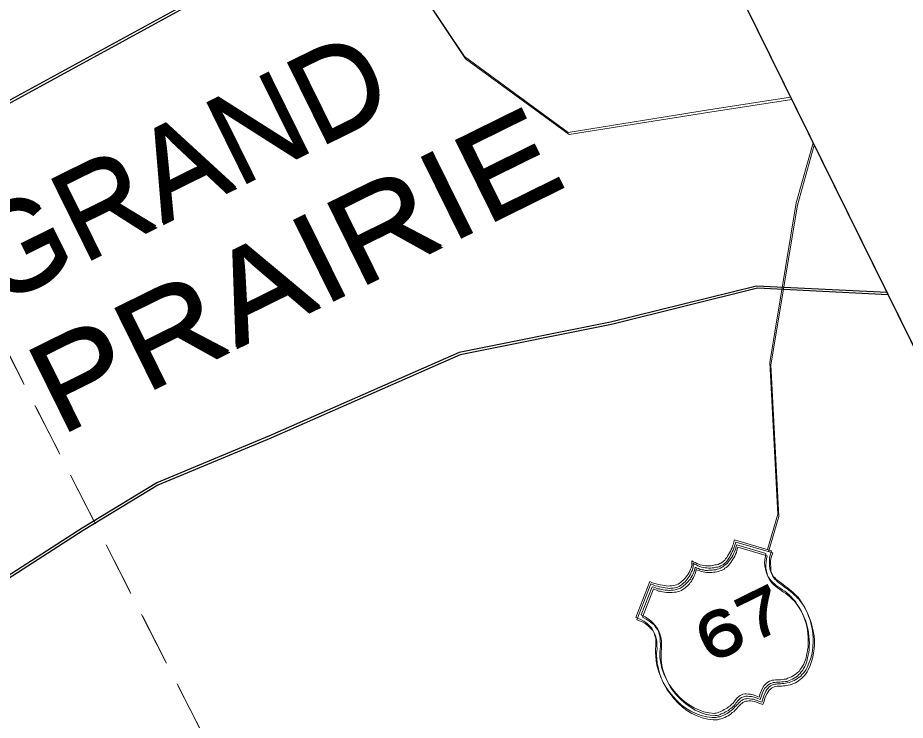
# Model space of a CAD drawing. Extents: x 2356606 to 2371222, y 6973096 to 6982644.
# Drawn here: x 2357437.7 to 2357539.9, y 6973680.4 to 6973761.2 of the extents above; entities that cross this region are included whole.
import ezdxf

# ---------------------------------------------------------------- set-up
doc = ezdxf.new("R2010")
doc.units = 0
doc.header["$LTSCALE"] = 2
doc.linetypes.add('MEDIUM_DASHED', pattern=[4.5, 3, -1.5])
doc.layers.add('62', color=7, linetype='Continuous', lineweight=13)
doc.layers.add('63', color=7, linetype='Continuous', lineweight=13)

msp = doc.modelspace()

# ---------------------------------------------------------------- linework, layer by layer
at = {"layer": '62', "linetype": 'MEDIUM_DASHED'}
msp.add_line((2357358.049, 6973876.711), (2357485.75, 6973626.399), dxfattribs=at)
at = {"layer": '62'}
msp.add_line((2357525.309, 6973703.86), (2357524.132, 6973699.792), dxfattribs=at)
at = {"layer": '62', "lineweight": 25}
for points in [[(2356999.05, 6973805.301), (2357204.965, 6973388.075), (2357608.13, 6973587.05), (2357402.214, 6974004.278)], [(2357505.855, 6973794.281), (2357494.638, 6973787.314), (2357477.945, 6973775.941), (2357457.618, 6973762.773), (2357434.819, 6973750.341), (2357408.769, 6973737.485), (2357380.527, 6973722.566), (2357364.72, 6973713.512)], [(2357537.893, 6973729.369), (2357522.87, 6973730.109), (2357506.064, 6973725.93), (2357488.655, 6973722.457), (2357466.842, 6973712.87), (2357453.859, 6973707.442), (2357445.268, 6973702.223), (2357430.768, 6973692.911), (2357420.094, 6973687.642), (2357412.343, 6973683.163)]]:
    msp.add_lwpolyline(points, dxfattribs=at)
at = {"layer": '62'}
for points in [[(2357526.798, 6973751.846), (2357517.36, 6973750.375), (2357501.195, 6973747.794), (2357489.256, 6973756.529), (2357484.812, 6973763.194), (2357480.012, 6973771.04), (2357477.267, 6973777.212), (2357474.788, 6973784.368), (2357471.174, 6973790.063), (2357467.234, 6973798.409)], [(2357529.386, 6973746.597), (2357527.44, 6973739.666), (2357524.387, 6973721.297), (2357525.309, 6973703.86)], [(2357508.987, 6973691.941), (2357510.58, 6973696.088), (2357510.83, 6973695.987), (2357511.082, 6973695.883), (2357511.332, 6973695.833), (2357511.572, 6973695.75), (2357511.797, 6973695.71), (2357512.035, 6973695.678), (2357512.237, 6973695.626), (2357512.478, 6973695.594), (2357512.689, 6973695.574), (2357512.882, 6973695.594), (2357513.103, 6973695.603), (2357513.284, 6973695.643), (2357513.495, 6973695.671), (2357513.657, 6973695.7), (2357513.84, 6973695.79), (2357514.008, 6973695.901), (2357514.12, 6973695.978), (2357514.232, 6973696.108), (2357514.382, 6973696.21), (2357514.524, 6973696.33), (2357514.648, 6973696.49), (2357514.758, 6973696.62), (2357514.88, 6973696.779), (2357515.001, 6973696.94), (2357515.103, 6973697.141), (2357515.195, 6973697.311), (2357515.266, 6973697.524), (2357515.366, 6973697.674), (2357515.408, 6973697.896), (2357515.439, 6973698.086), (2357515.44, 6973698.287), (2357515.441, 6973698.489), (2357515.621, 6973698.377), (2357515.825, 6973698.276), (2357516.003, 6973698.164), (2357516.214, 6973698.093), (2357516.404, 6973698.01), (2357516.616, 6973697.988), (2357516.818, 6973697.937), (2357517.028, 6973697.917), (2357517.23, 6973697.914), (2357517.441, 6973697.893), (2357517.652, 6973697.922), (2357517.844, 6973697.941), (2357518.065, 6973698.003), (2357518.238, 6973698.01), (2357518.458, 6973698.069), (2357518.639, 6973698.159), (2357518.781, 6973698.229), (2357518.942, 6973698.308), (2357519.053, 6973698.438), (2357519.216, 6973698.568), (2357519.318, 6973698.719), (2357519.448, 6973698.86), (2357519.541, 6973699.03), (2357519.663, 6973699.19), (2357519.745, 6973699.381), (2357519.866, 6973699.592), (2357519.946, 6973699.782), (2357520.05, 6973699.983), (2357520.11, 6973700.214), (2357520.221, 6973700.446), (2357520.265, 6973700.668), (2357520.345, 6973700.908), (2357524.605, 6973699.647), (2357524.471, 6973699.258), (2357524.359, 6973698.825), (2357524.345, 6973698.392), (2357524.375, 6973697.98), (2357524.405, 6973697.567), (2357524.521, 6973697.223), (2357524.632, 6973696.952), (2357524.74, 6973696.778), (2357524.842, 6973696.628), (2357525.001, 6973696.508), (2357525.131, 6973696.344), (2357525.321, 6973696.212), (2357525.52, 6973696.061), (2357525.725, 6973695.909), (2357525.933, 6973695.736), (2357526.174, 6973695.555), (2357526.405, 6973695.394), (2357526.635, 6973695.231), (2357526.864, 6973695.019), (2357527.075, 6973694.846), (2357527.295, 6973694.652), (2357527.466, 6973694.46), (2357527.657, 6973694.28), (2357527.796, 6973694.048), (2357528.126, 6973693.583), (2357528.417, 6973693.097), (2357528.644, 6973692.633), (2357528.841, 6973692.129), (2357529.028, 6973691.646), (2357529.159, 6973691.133), (2357529.276, 6973690.638), (2357529.356, 6973690.124), (2357529.403, 6973689.622), (2357529.402, 6973689.118)], [(2357528.7, 6973687.893), (2357528.749, 6973688.194), (2357528.802, 6973688.548), (2357528.805, 6973688.9), (2357528.819, 6973689.283), (2357528.797, 6973689.674), (2357528.772, 6973690.088), (2357528.732, 6973690.522), (2357528.655, 6973690.934), (2357528.537, 6973691.377), (2357528.397, 6973691.81), (2357528.24, 6973692.233), (2357528.03, 6973692.657), (2357527.791, 6973693.092), (2357527.56, 6973693.455), (2357527.34, 6973693.797), (2357527.102, 6973694.081), (2357526.85, 6973694.334), (2357526.611, 6973694.566), (2357526.351, 6973694.79), (2357526.111, 6973694.973), (2357525.849, 6973695.142), (2357525.589, 6973695.317), (2357525.378, 6973695.487), (2357525.148, 6973695.65), (2357524.938, 6973695.822), (2357524.728, 6973695.994), (2357524.557, 6973696.188), (2357524.396, 6973696.359), (2357524.236, 6973696.581), (2357524.096, 6973696.864), (2357523.977, 6973697.205), (2357523.89, 6973697.54), (2357523.82, 6973697.88), (2357523.793, 6973698.242), (2357523.834, 6973698.615), (2357523.887, 6973698.969), (2357523.957, 6973699.329), (2357520.604, 6973700.333), (2357520.531, 6973700.123), (2357520.48, 6973699.919), (2357520.42, 6973699.689), (2357520.339, 6973699.5), (2357520.236, 6973699.297), (2357520.134, 6973699.098), (2357520.025, 6973698.917), (2357519.911, 6973698.737), (2357519.769, 6973698.567), (2357519.658, 6973698.387), (2357519.514, 6973698.216), (2357519.395, 6973698.106), (2357519.233, 6973697.977), (2357519.102, 6973697.885), (2357519, 6973697.786), (2357518.859, 6973697.714), (2357518.717, 6973697.644), (2357518.525, 6973697.576), (2357518.356, 6973697.518), (2357518.182, 6973697.458), (2357517.97, 6973697.427), (2357517.8, 6973697.419), (2357517.589, 6973697.391), (2357517.388, 6973697.392), (2357517.216, 6973697.383), (2357516.965, 6973697.384), (2357516.794, 6973697.424), (2357516.604, 6973697.457), (2357516.384, 6973697.496), (2357516.212, 6973697.587), (2357516.011, 6973697.64), (2357515.801, 6973697.763), (2357515.759, 6973697.541), (2357515.729, 6973697.349), (2357515.647, 6973697.159), (2357515.574, 6973696.999), (2357515.503, 6973696.836), (2357515.423, 6973696.696), (2357515.312, 6973696.518), (2357515.262, 6973696.367), (2357515.117, 6973696.248), (2357515.018, 6973696.097), (2357514.895, 6973695.984), (2357514.784, 6973695.856), (2357514.653, 6973695.765), (2357514.521, 6973695.626), (2357514.391, 6973695.536), (2357514.259, 6973695.444), (2357514.106, 6973695.346), (2357513.905, 6973695.247), (2357513.726, 6973695.208), (2357513.501, 6973695.148), (2357513.291, 6973695.119), (2357513.048, 6973695.099), (2357512.809, 6973695.082), (2357512.616, 6973695.112), (2357512.366, 6973695.112), (2357512.135, 6973695.124), (2357511.914, 6973695.165), (2357511.702, 6973695.238), (2357511.461, 6973695.269), (2357511.239, 6973695.361)], [(2357510.87, 6973695.503), (2357509.612, 6973692.25), (2357510.043, 6973692.036), (2357510.384, 6973691.803), (2357510.695, 6973691.579), (2357510.956, 6973691.357), (2357511.166, 6973691.085), (2357511.356, 6973690.851), (2357511.516, 6973690.63), (2357511.607, 6973690.347), (2357511.674, 6973690.056), (2357511.754, 6973689.791), (2357511.802, 6973689.49), (2357511.799, 6973689.189), (2357511.81, 6973688.918), (2357511.808, 6973688.614), (2357511.775, 6973688.325), (2357511.755, 6973688.012), (2357511.76, 6973687.338), (2357511.858, 6973686.683), (2357511.985, 6973686.069), (2357512.213, 6973685.454), (2357512.493, 6973684.837), (2357512.81, 6973684.243), (2357513.2, 6973683.707), (2357513.621, 6973683.211), (2357514.091, 6973682.715), (2357514.601, 6973682.291), (2357515.124, 6973681.896), (2357515.685, 6973681.572), (2357516.228, 6973681.339), (2357516.82, 6973681.102), (2357517.402, 6973680.989), (2357517.986, 6973680.926), (2357518.097, 6973680.956), (2357518.229, 6973680.946), (2357518.389, 6973680.974), (2357518.552, 6973681.055), (2357518.672, 6973681.114), (2357518.846, 6973681.174), (2357519.005, 6973681.253), (2357519.157, 6973681.352), (2357519.338, 6973681.443), (2357519.499, 6973681.521), (2357519.631, 6973681.662), (2357519.782, 6973681.762), (2357519.933, 6973681.863), (2357520.045, 6973681.993), (2357520.167, 6973682.103), (2357520.267, 6973682.203), (2357520.37, 6973682.352), (2357520.46, 6973682.473), (2357520.551, 6973682.594), (2357520.652, 6973682.693), (2357520.784, 6973682.832), (2357520.876, 6973682.903), (2357521.005, 6973682.994), (2357521.147, 6973683.064), (2357521.301, 6973683.114), (2357521.52, 6973683.172), (2357521.692, 6973683.18), (2357521.914, 6973683.141), (2357522.165, 6973683.139), (2357522.467, 6973683.037), (2357522.807, 6973682.954), (2357523.159, 6973682.801), (2357523.302, 6973683.222), (2357523.445, 6973683.545), (2357523.559, 6973683.826), (2357523.709, 6973684.076), (2357523.872, 6973684.257), (2357524.002, 6973684.397), (2357524.163, 6973684.526), (2357524.346, 6973684.617), (2357524.517, 6973684.676), (2357524.669, 6973684.726), (2357524.859, 6973684.744), (2357525.051, 6973684.764), (2357525.241, 6973684.783), (2357525.423, 6973684.771), (2357525.633, 6973684.801), (2357525.856, 6973684.81), (2357526.057, 6973684.859), (2357526.278, 6973684.868), (2357526.481, 6973684.968), (2357526.672, 6973685.037), (2357526.884, 6973685.115), (2357527.076, 6973685.236), (2357527.247, 6973685.346), (2357527.44, 6973685.465), (2357527.588, 6973685.616), (2357527.773, 6973685.757), (2357527.895, 6973685.966), (2357528.056, 6973686.146), (2357528.16, 6973686.347), (2357528.301, 6973686.568), (2357528.402, 6973686.82), (2357528.503, 6973687.07), (2357528.564, 6973687.301), (2357528.618, 6973687.603), (2357528.7, 6973687.893)], [(2357511.239, 6973695.361), (2357511.048, 6973695.441), (2357510.87, 6973695.503)], [(2357509.91, 6973691.543), (2357509.499, 6973691.765), (2357508.987, 6973691.941)], [(2357529.402, 6973689.118), (2357529.366, 6973688.626), (2357529.304, 6973688.142), (2357529.223, 6973687.65), (2357529.069, 6973687.149), (2357528.894, 6973686.686), (2357528.701, 6973686.214), (2357528.568, 6973685.973), (2357528.427, 6973685.751), (2357528.274, 6973685.552), (2357528.102, 6973685.394), (2357527.961, 6973685.223), (2357527.779, 6973685.08), (2357527.577, 6973684.93), (2357527.407, 6973684.822), (2357527.215, 6973684.701), (2357527.001, 6973684.623), (2357526.822, 6973684.534), (2357526.62, 6973684.483), (2357526.388, 6973684.446), (2357526.215, 6973684.385), (2357526.026, 6973684.368), (2357525.833, 6973684.346), (2357525.642, 6973684.328), (2357525.47, 6973684.319), (2357525.289, 6973684.332), (2357525.127, 6973684.299), (2357524.967, 6973684.271), (2357524.786, 6973684.232), (2357524.635, 6973684.181), (2357524.473, 6973684.101), (2357524.332, 6973683.981), (2357524.2, 6973683.841), (2357524.069, 6973683.652), (2357523.957, 6973683.471), (2357523.815, 6973683.198), (2357523.692, 6973682.941), (2357523.61, 6973682.596), (2357523.478, 6973682.205), (2357523.136, 6973682.337), (2357522.815, 6973682.431), (2357522.534, 6973682.544), (2357522.292, 6973682.573), (2357522.071, 6973682.614), (2357521.859, 6973682.637), (2357521.698, 6973682.607), (2357521.528, 6973682.599), (2357521.395, 6973682.557), (2357521.254, 6973682.489), (2357521.162, 6973682.418), (2357521.042, 6973682.309), (2357520.932, 6973682.23), (2357520.83, 6973682.129), (2357520.72, 6973681.999), (2357520.598, 6973681.89), (2357520.528, 6973681.777), (2357520.386, 6973681.659), (2357520.255, 6973681.517), (2357520.123, 6973681.379), (2357519.951, 6973681.267), (2357519.811, 6973681.148), (2357519.627, 6973681.009), (2357519.476, 6973680.909), (2357519.273, 6973680.809), (2357519.112, 6973680.729), (2357518.912, 6973680.629), (2357518.679, 6973680.541), (2357518.468, 6973680.512), (2357518.245, 6973680.452), (2357518.005, 6973680.432), (2357517.751, 6973680.436), (2357517.14, 6973680.509), (2357516.504, 6973680.672), (2357515.892, 6973680.894), (2357515.301, 6973681.18), (2357514.728, 6973681.526), (2357514.218, 6973681.9), (2357513.737, 6973682.365), (2357513.266, 6973682.862), (2357512.866, 6973683.367), (2357512.474, 6973683.902), (2357512.138, 6973684.488), (2357511.849, 6973685.074), (2357511.611, 6973685.706), (2357511.443, 6973686.304), (2357511.326, 6973686.947), (2357511.268, 6973687.571), (2357511.248, 6973687.811), (2357511.25, 6973688.064), (2357511.262, 6973688.347), (2357511.294, 6973688.639), (2357511.276, 6973688.929), (2357511.277, 6973689.23), (2357511.271, 6973689.553), (2357511.179, 6973689.835), (2357511.1, 6973690.149), (2357510.951, 6973690.45), (2357510.811, 6973690.734), (2357510.551, 6973691.007), (2357510.29, 6973691.279), (2357509.91, 6973691.543)]]:
    msp.add_lwpolyline(points, dxfattribs=at)
at = {"layer": '63', "linetype": 'MEDIUM_DASHED'}
msp.add_line((2357357.919, 6973876.974), (2357485.62, 6973626.662), dxfattribs=at)
at = {"layer": '63'}
msp.add_line((2357525.179, 6973704.123), (2357524.002, 6973700.055), dxfattribs=at)
at = {"layer": '63', "lineweight": 25}
for points in [[(2356998.92, 6973805.564), (2357204.835, 6973388.338), (2357608, 6973587.313), (2357402.084, 6974004.541)], [(2357505.725, 6973794.544), (2357494.508, 6973787.577), (2357477.815, 6973776.204), (2357457.488, 6973763.036), (2357434.689, 6973750.604), (2357408.639, 6973737.748), (2357380.397, 6973722.829), (2357364.59, 6973713.775)], [(2357537.763, 6973729.632), (2357522.74, 6973730.372), (2357505.934, 6973726.193), (2357488.525, 6973722.72), (2357466.712, 6973713.133), (2357453.729, 6973707.705), (2357445.138, 6973702.486), (2357430.638, 6973693.174), (2357419.964, 6973687.905), (2357412.213, 6973683.426)]]:
    msp.add_lwpolyline(points, dxfattribs=at)
at = {"layer": '63'}
for points in [[(2357526.668, 6973752.109), (2357517.23, 6973750.638), (2357501.065, 6973748.057), (2357489.126, 6973756.792), (2357484.682, 6973763.457), (2357479.882, 6973771.303), (2357477.137, 6973777.475), (2357474.658, 6973784.631), (2357471.044, 6973790.326), (2357467.104, 6973798.672)], [(2357529.256, 6973746.86), (2357527.31, 6973739.929), (2357524.257, 6973721.56), (2357525.179, 6973704.123)], [(2357508.857, 6973692.204), (2357510.45, 6973696.351), (2357510.7, 6973696.25), (2357510.952, 6973696.146), (2357511.202, 6973696.096), (2357511.442, 6973696.013), (2357511.667, 6973695.973), (2357511.905, 6973695.941), (2357512.107, 6973695.889), (2357512.348, 6973695.857), (2357512.559, 6973695.837), (2357512.752, 6973695.857), (2357512.973, 6973695.866), (2357513.154, 6973695.906), (2357513.365, 6973695.934), (2357513.527, 6973695.963), (2357513.71, 6973696.053), (2357513.878, 6973696.164), (2357513.99, 6973696.241), (2357514.102, 6973696.371), (2357514.252, 6973696.473), (2357514.394, 6973696.593), (2357514.518, 6973696.753), (2357514.628, 6973696.883), (2357514.75, 6973697.042), (2357514.871, 6973697.203), (2357514.973, 6973697.404), (2357515.065, 6973697.574), (2357515.136, 6973697.787), (2357515.236, 6973697.937), (2357515.278, 6973698.159), (2357515.309, 6973698.349), (2357515.31, 6973698.55), (2357515.311, 6973698.752), (2357515.491, 6973698.64), (2357515.695, 6973698.539), (2357515.873, 6973698.427), (2357516.084, 6973698.356), (2357516.274, 6973698.273), (2357516.486, 6973698.251), (2357516.688, 6973698.2), (2357516.898, 6973698.18), (2357517.1, 6973698.177), (2357517.311, 6973698.156), (2357517.522, 6973698.185), (2357517.714, 6973698.204), (2357517.935, 6973698.266), (2357518.108, 6973698.273), (2357518.328, 6973698.332), (2357518.509, 6973698.422), (2357518.651, 6973698.492), (2357518.812, 6973698.571), (2357518.923, 6973698.701), (2357519.086, 6973698.831), (2357519.188, 6973698.982), (2357519.318, 6973699.123), (2357519.411, 6973699.293), (2357519.533, 6973699.453), (2357519.615, 6973699.644), (2357519.736, 6973699.855), (2357519.816, 6973700.045), (2357519.92, 6973700.246), (2357519.98, 6973700.477), (2357520.091, 6973700.709), (2357520.135, 6973700.931), (2357520.215, 6973701.171), (2357524.475, 6973699.91), (2357524.341, 6973699.521), (2357524.229, 6973699.088), (2357524.215, 6973698.655), (2357524.245, 6973698.243), (2357524.275, 6973697.83), (2357524.391, 6973697.486), (2357524.502, 6973697.215), (2357524.61, 6973697.041), (2357524.712, 6973696.891), (2357524.871, 6973696.771), (2357525.001, 6973696.607), (2357525.191, 6973696.475), (2357525.39, 6973696.324), (2357525.595, 6973696.172), (2357525.803, 6973695.999), (2357526.044, 6973695.818), (2357526.275, 6973695.657), (2357526.505, 6973695.494), (2357526.734, 6973695.282), (2357526.945, 6973695.109), (2357527.165, 6973694.915), (2357527.336, 6973694.723), (2357527.527, 6973694.543), (2357527.666, 6973694.311), (2357527.996, 6973693.846), (2357528.287, 6973693.36), (2357528.514, 6973692.896), (2357528.711, 6973692.392), (2357528.898, 6973691.909), (2357529.029, 6973691.396), (2357529.146, 6973690.901), (2357529.226, 6973690.387), (2357529.273, 6973689.885), (2357529.272, 6973689.381)], [(2357528.57, 6973688.156), (2357528.619, 6973688.457), (2357528.672, 6973688.811), (2357528.675, 6973689.163), (2357528.689, 6973689.546), (2357528.667, 6973689.937), (2357528.642, 6973690.351), (2357528.602, 6973690.785), (2357528.525, 6973691.197), (2357528.407, 6973691.64), (2357528.267, 6973692.073), (2357528.11, 6973692.496), (2357527.9, 6973692.92), (2357527.661, 6973693.355), (2357527.43, 6973693.718), (2357527.21, 6973694.06), (2357526.972, 6973694.344), (2357526.72, 6973694.597), (2357526.481, 6973694.829), (2357526.221, 6973695.053), (2357525.981, 6973695.236), (2357525.719, 6973695.405), (2357525.459, 6973695.58), (2357525.248, 6973695.75), (2357525.018, 6973695.913), (2357524.808, 6973696.085), (2357524.598, 6973696.257), (2357524.427, 6973696.451), (2357524.266, 6973696.622), (2357524.106, 6973696.844), (2357523.966, 6973697.127), (2357523.847, 6973697.468), (2357523.76, 6973697.803), (2357523.69, 6973698.143), (2357523.663, 6973698.505), (2357523.704, 6973698.878), (2357523.757, 6973699.232), (2357523.827, 6973699.592), (2357520.474, 6973700.596), (2357520.401, 6973700.386), (2357520.35, 6973700.182), (2357520.29, 6973699.952), (2357520.209, 6973699.763), (2357520.106, 6973699.56), (2357520.004, 6973699.361), (2357519.895, 6973699.18), (2357519.781, 6973699), (2357519.639, 6973698.83), (2357519.528, 6973698.65), (2357519.384, 6973698.479), (2357519.265, 6973698.369), (2357519.103, 6973698.24), (2357518.972, 6973698.148), (2357518.87, 6973698.049), (2357518.729, 6973697.977), (2357518.587, 6973697.907), (2357518.395, 6973697.839), (2357518.226, 6973697.781), (2357518.052, 6973697.721), (2357517.84, 6973697.69), (2357517.67, 6973697.682), (2357517.459, 6973697.654), (2357517.258, 6973697.655), (2357517.086, 6973697.646), (2357516.835, 6973697.647), (2357516.664, 6973697.687), (2357516.474, 6973697.72), (2357516.254, 6973697.759), (2357516.082, 6973697.85), (2357515.881, 6973697.903), (2357515.671, 6973698.026), (2357515.629, 6973697.804), (2357515.599, 6973697.612), (2357515.517, 6973697.422), (2357515.444, 6973697.262), (2357515.373, 6973697.099), (2357515.293, 6973696.959), (2357515.182, 6973696.781), (2357515.132, 6973696.63), (2357514.987, 6973696.511), (2357514.888, 6973696.36), (2357514.765, 6973696.247), (2357514.654, 6973696.119), (2357514.523, 6973696.028), (2357514.391, 6973695.889), (2357514.261, 6973695.799), (2357514.129, 6973695.707), (2357513.976, 6973695.609), (2357513.775, 6973695.51), (2357513.596, 6973695.471), (2357513.371, 6973695.411), (2357513.161, 6973695.382), (2357512.918, 6973695.362), (2357512.679, 6973695.345), (2357512.486, 6973695.375), (2357512.236, 6973695.375), (2357512.005, 6973695.387), (2357511.784, 6973695.428), (2357511.572, 6973695.501), (2357511.331, 6973695.532), (2357511.109, 6973695.624)], [(2357510.74, 6973695.766), (2357509.482, 6973692.513), (2357509.913, 6973692.299), (2357510.254, 6973692.066), (2357510.565, 6973691.842), (2357510.826, 6973691.62), (2357511.036, 6973691.348), (2357511.226, 6973691.114), (2357511.386, 6973690.893), (2357511.477, 6973690.61), (2357511.544, 6973690.319), (2357511.624, 6973690.054), (2357511.672, 6973689.753), (2357511.669, 6973689.452), (2357511.68, 6973689.181), (2357511.678, 6973688.877), (2357511.645, 6973688.588), (2357511.625, 6973688.275), (2357511.63, 6973687.601), (2357511.728, 6973686.946), (2357511.855, 6973686.332), (2357512.083, 6973685.717), (2357512.363, 6973685.1), (2357512.68, 6973684.506), (2357513.07, 6973683.97), (2357513.491, 6973683.474), (2357513.961, 6973682.978), (2357514.471, 6973682.554), (2357514.994, 6973682.159), (2357515.555, 6973681.835), (2357516.098, 6973681.602), (2357516.69, 6973681.365), (2357517.272, 6973681.252), (2357517.856, 6973681.189), (2357517.967, 6973681.219), (2357518.099, 6973681.209), (2357518.259, 6973681.237), (2357518.422, 6973681.318), (2357518.542, 6973681.377), (2357518.716, 6973681.437), (2357518.875, 6973681.516), (2357519.027, 6973681.615), (2357519.208, 6973681.706), (2357519.369, 6973681.784), (2357519.501, 6973681.925), (2357519.652, 6973682.025), (2357519.803, 6973682.126), (2357519.915, 6973682.256), (2357520.037, 6973682.366), (2357520.137, 6973682.466), (2357520.24, 6973682.615), (2357520.33, 6973682.736), (2357520.421, 6973682.857), (2357520.522, 6973682.956), (2357520.654, 6973683.095), (2357520.746, 6973683.166), (2357520.875, 6973683.257), (2357521.017, 6973683.327), (2357521.171, 6973683.377), (2357521.39, 6973683.435), (2357521.562, 6973683.443), (2357521.784, 6973683.404), (2357522.035, 6973683.402), (2357522.337, 6973683.3), (2357522.677, 6973683.217), (2357523.029, 6973683.064), (2357523.172, 6973683.485), (2357523.315, 6973683.808), (2357523.429, 6973684.089), (2357523.579, 6973684.339), (2357523.742, 6973684.52), (2357523.872, 6973684.66), (2357524.033, 6973684.789), (2357524.216, 6973684.88), (2357524.387, 6973684.939), (2357524.539, 6973684.989), (2357524.729, 6973685.007), (2357524.921, 6973685.027), (2357525.111, 6973685.046), (2357525.293, 6973685.034), (2357525.503, 6973685.064), (2357525.726, 6973685.073), (2357525.927, 6973685.122), (2357526.148, 6973685.131), (2357526.351, 6973685.231), (2357526.542, 6973685.3), (2357526.754, 6973685.378), (2357526.946, 6973685.499), (2357527.117, 6973685.609), (2357527.31, 6973685.728), (2357527.458, 6973685.879), (2357527.643, 6973686.02), (2357527.765, 6973686.229), (2357527.926, 6973686.409), (2357528.03, 6973686.61), (2357528.171, 6973686.831), (2357528.272, 6973687.083), (2357528.373, 6973687.333), (2357528.434, 6973687.564), (2357528.488, 6973687.866), (2357528.57, 6973688.156)], [(2357511.109, 6973695.624), (2357510.918, 6973695.704), (2357510.74, 6973695.766)], [(2357509.78, 6973691.806), (2357509.369, 6973692.028), (2357508.857, 6973692.204)], [(2357529.272, 6973689.381), (2357529.236, 6973688.889), (2357529.174, 6973688.405), (2357529.093, 6973687.913), (2357528.939, 6973687.412), (2357528.764, 6973686.949), (2357528.571, 6973686.477), (2357528.438, 6973686.236), (2357528.297, 6973686.014), (2357528.144, 6973685.815), (2357527.972, 6973685.657), (2357527.831, 6973685.486), (2357527.649, 6973685.343), (2357527.447, 6973685.193), (2357527.277, 6973685.085), (2357527.085, 6973684.964), (2357526.871, 6973684.886), (2357526.692, 6973684.797), (2357526.49, 6973684.746), (2357526.258, 6973684.709), (2357526.085, 6973684.648), (2357525.896, 6973684.631), (2357525.703, 6973684.609), (2357525.512, 6973684.591), (2357525.34, 6973684.582), (2357525.159, 6973684.595), (2357524.997, 6973684.562), (2357524.837, 6973684.534), (2357524.656, 6973684.495), (2357524.505, 6973684.444), (2357524.343, 6973684.364), (2357524.202, 6973684.244), (2357524.07, 6973684.104), (2357523.939, 6973683.915), (2357523.827, 6973683.734), (2357523.685, 6973683.461), (2357523.562, 6973683.204), (2357523.48, 6973682.859), (2357523.348, 6973682.468), (2357523.006, 6973682.6), (2357522.685, 6973682.694), (2357522.404, 6973682.807), (2357522.162, 6973682.836), (2357521.941, 6973682.877), (2357521.729, 6973682.9), (2357521.568, 6973682.87), (2357521.398, 6973682.862), (2357521.265, 6973682.82), (2357521.124, 6973682.752), (2357521.032, 6973682.681), (2357520.912, 6973682.572), (2357520.802, 6973682.493), (2357520.7, 6973682.392), (2357520.59, 6973682.262), (2357520.468, 6973682.153), (2357520.398, 6973682.04), (2357520.256, 6973681.922), (2357520.125, 6973681.78), (2357519.993, 6973681.642), (2357519.821, 6973681.53), (2357519.681, 6973681.411), (2357519.497, 6973681.272), (2357519.346, 6973681.172), (2357519.143, 6973681.072), (2357518.982, 6973680.992), (2357518.782, 6973680.892), (2357518.549, 6973680.804), (2357518.338, 6973680.775), (2357518.115, 6973680.715), (2357517.875, 6973680.695), (2357517.621, 6973680.699), (2357517.01, 6973680.772), (2357516.374, 6973680.935), (2357515.762, 6973681.157), (2357515.171, 6973681.443), (2357514.598, 6973681.789), (2357514.088, 6973682.163), (2357513.607, 6973682.628), (2357513.136, 6973683.125), (2357512.736, 6973683.63), (2357512.344, 6973684.165), (2357512.008, 6973684.751), (2357511.719, 6973685.337), (2357511.481, 6973685.969), (2357511.313, 6973686.567), (2357511.196, 6973687.21), (2357511.138, 6973687.834), (2357511.118, 6973688.074), (2357511.12, 6973688.327), (2357511.132, 6973688.61), (2357511.164, 6973688.902), (2357511.146, 6973689.192), (2357511.147, 6973689.493), (2357511.141, 6973689.816), (2357511.049, 6973690.098), (2357510.97, 6973690.412), (2357510.821, 6973690.713), (2357510.681, 6973690.997), (2357510.421, 6973691.27), (2357510.16, 6973691.542), (2357509.78, 6973691.806)]]:
    msp.add_lwpolyline(points, dxfattribs=at)

# ---------------------------------------------------------------- texts
at = {"layer": '62'}
for s, height, width, p in [('GRAND', 10.21, 1.05, (2357435.168, 6973727.828)), ('PRAIRIE', 10.21, 1.2, (2357442.497, 6973712.978)), ('67', 5.099, 1.4, (2357517.312, 6973686.767))]:
    msp.add_text(s, height=height, rotation=26.268, dxfattribs=dict(at, width=width)).set_placement(p)
at = {"layer": '63'}
for s, height, width, p in [('GRAND', 10.21, 1.05, (2357435.038, 6973728.092)), ('PRAIRIE', 10.21, 1.2, (2357442.367, 6973713.242)), ('67', 5.099, 1.4, (2357517.182, 6973687.031))]:
    msp.add_text(s, height=height, rotation=26.268, dxfattribs=dict(at, width=width)).set_placement(p)

doc.saveas('drawing.dxf')
